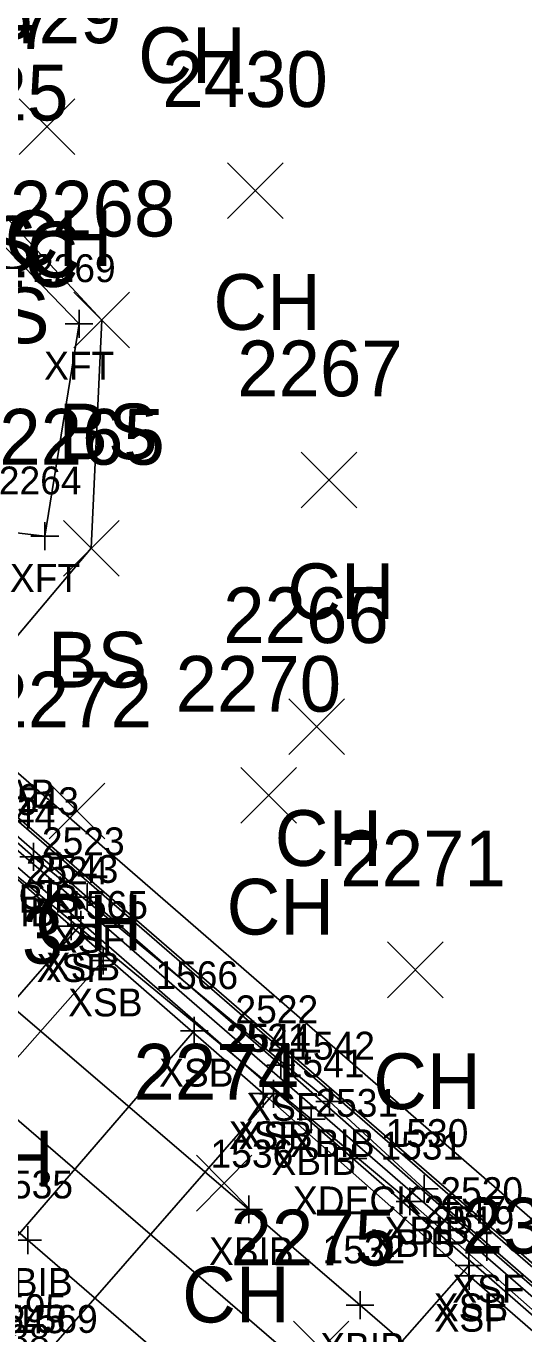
# Model space of a CAD drawing. Extents: x 1459992 to 1461532, y 647785 to 648535.
# Drawn here: x 1461313.18 to 1461331.07, y 648190.36 to 648237.31 of the extents above; entities that cross this region are included whole.
import ezdxf

# ---------------------------------------------------------------- set-up
doc = ezdxf.new("R2010")
doc.units = 0
for name, color, linetype in [('B_A', 7, 'Continuous'), ('B_C', 7, 'Continuous'), ('B_I', 7, 'Continuous'), ('B_TIC', 7, 'Continuous'), ('BB', 7, 'Continuous'), ('BDEFAULT', 7, 'Continuous'), ('BELB', 7, 'Continuous'), ('BFT', 7, 'Continuous'), ('L_A', 7, 'Continuous'), ('L_I', 7, 'Continuous'), ('L_TIC', 7, 'Continuous'), ('LELB', 7, 'Continuous')]:
    doc.layers.add(name, color=color, linetype=linetype)

msp = doc.modelspace()

# ---------------------------------------------------------------- linework, layer by layer
at = {"layer": 'B_TIC'}
for p, q in [((1461315.084, 648226.618), (1461315.16, 648226.618)), ((1461313.855, 648218.998), (1461313.931, 648218.998)), ((1461313.452, 648207.484), (1461313.528, 648207.484)), ((1461315.381, 648206.043), (1461315.456, 648206.043)), ((1461314.8, 648204.994), (1461314.876, 648204.994)), ((1461315.154, 648205.052), (1461315.229, 648205.052)), ((1461315.957, 648203.76), (1461316.032, 648203.76)), ((1461319.228, 648201.238), (1461319.303, 648201.238)), ((1461322.339, 648200.012), (1461322.414, 648200.012)), ((1461321.707, 648198.993), (1461321.782, 648198.993)), ((1461322.073, 648198.982), (1461322.148, 648198.982)), ((1461324.094, 648198.708), (1461324.169, 648198.708)), ((1461323.433, 648198.068), (1461323.508, 648198.068)), ((1461324.929, 648196.655), (1461325.004, 648196.655)), ((1461327.496, 648195.57), (1461327.572, 648195.57)), ((1461321.185, 648194.832), (1461321.261, 648194.832)), ((1461326.981, 648195.119), (1461327.057, 648195.119)), ((1461313.24, 648193.724), (1461313.315, 648193.724)), ((1461329.746, 648193.486), (1461329.822, 648193.486)), ((1461329.103, 648192.816), (1461329.178, 648192.816)), ((1461329.108, 648192.44), (1461329.184, 648192.44)), ((1461325.186, 648191.393), (1461325.262, 648191.393))]:
    msp.add_line(p, q, dxfattribs=at)
for points in [[(1461315.081, 648226.118), (1461315.081, 648227.118)], [(1461314.581, 648226.618), (1461315.581, 648226.618)], [(1461313.852, 648218.498), (1461313.852, 648219.498)], [(1461313.352, 648218.998), (1461314.352, 648218.998)], [(1461313.449, 648206.984), (1461313.449, 648207.984)], [(1461312.949, 648207.484), (1461313.949, 648207.484)], [(1461315.377, 648205.543), (1461315.377, 648206.543)], [(1461314.877, 648206.043), (1461315.877, 648206.043)], [(1461314.797, 648204.494), (1461314.797, 648205.494)], [(1461315.15, 648204.552), (1461315.15, 648205.552)], [(1461314.297, 648204.994), (1461315.297, 648204.994)], [(1461314.65, 648205.052), (1461315.65, 648205.052)], [(1461315.953, 648203.26), (1461315.953, 648204.26)], [(1461315.453, 648203.76), (1461316.453, 648203.76)], [(1461319.224, 648200.738), (1461319.224, 648201.738)], [(1461318.724, 648201.238), (1461319.724, 648201.238)], [(1461322.335, 648199.512), (1461322.335, 648200.512)], [(1461321.835, 648200.012), (1461322.835, 648200.012)], [(1461321.703, 648198.492), (1461321.703, 648199.493)], [(1461322.069, 648198.482), (1461322.069, 648199.482)], [(1461324.09, 648198.208), (1461324.09, 648199.208)], [(1461321.203, 648198.993), (1461322.203, 648198.993)], [(1461321.569, 648198.982), (1461322.569, 648198.982)], [(1461323.59, 648198.708), (1461324.59, 648198.708)], [(1461323.429, 648197.568), (1461323.429, 648198.568)], [(1461322.929, 648198.068), (1461323.929, 648198.068)], [(1461324.925, 648196.155), (1461324.925, 648197.155)], [(1461324.425, 648196.655), (1461325.425, 648196.655)], [(1461327.493, 648195.07), (1461327.493, 648196.07)], [(1461321.182, 648194.332), (1461321.182, 648195.332)], [(1461326.978, 648194.619), (1461326.978, 648195.619)], [(1461326.993, 648195.57), (1461327.993, 648195.57)], [(1461320.682, 648194.832), (1461321.682, 648194.832)], [(1461326.478, 648195.119), (1461327.478, 648195.119)], [(1461313.236, 648193.224), (1461313.236, 648194.224)], [(1461329.743, 648192.986), (1461329.743, 648193.986)], [(1461312.736, 648193.724), (1461313.736, 648193.724)], [(1461329.243, 648193.486), (1461330.243, 648193.486)], [(1461329.099, 648192.316), (1461329.099, 648193.316)], [(1461328.599, 648192.816), (1461329.599, 648192.816)], [(1461329.105, 648191.94), (1461329.105, 648192.94)], [(1461328.605, 648192.44), (1461329.605, 648192.44)], [(1461325.183, 648190.893), (1461325.183, 648191.893)], [(1461324.683, 648191.393), (1461325.683, 648191.393)]]:
    msp.add_lwpolyline(points, dxfattribs=at)
at = {"layer": 'BB'}
for points in [[(1461294.86, 648223.307), (1461364.242, 648163.24)], [(1461361.677, 648166.016), (1461348.554, 648177.299), (1461327.493, 648195.57), (1461324.09, 648198.708), (1461313.449, 648207.484), (1461303.185, 648216.496), (1461300.834, 648218.513)], [(1461361.208, 648165.406), (1461348.067, 648176.515), (1461326.978, 648195.119), (1461323.429, 648198.068), (1461312.601, 648206.996), (1461302.604, 648215.891), (1461300.353, 648217.975)], [(1461357.803, 648164.521), (1461346.033, 648173.409), (1461325.183, 648191.393), (1461321.182, 648194.832), (1461311.295, 648203.276), (1461301.649, 648211.621), (1461295.127, 648216.651)], [(1461353.847, 648159.998), (1461342.222, 648168.764), (1461326.194, 648182.545), (1461313.236, 648193.724), (1461305.462, 648200.447), (1461296.007, 648208.646)], [(1461306.331, 648194.965), (1461315.15, 648205.052)], [(1461315.953, 648203.76), (1461307.671, 648194.424)], [(1461319.224, 648201.238), (1461310.969, 648191.688)], [(1461322.069, 648198.982), (1461313.243, 648188.887)], [(1461320.229, 648182.764), (1461329.099, 648192.816)]]:
    msp.add_lwpolyline(points, dxfattribs=at)
at = {"layer": 'BDEFAULT'}
for points in [[(1461366.38, 648164.112), (1461295.255, 648225.766)], [(1461362.149, 648166.267), (1461362.72, 648165.994), (1461364.469, 648164.112), (1461295.876, 648223.48), (1461297.915, 648221.839), (1461297.913, 648221.848)], [(1461362.149, 648166.267), (1461297.913, 648221.848)], [(1461361.121, 648166.284), (1461352.416, 648173.806), (1461344.425, 648180.701), (1461343.816, 648181.296), (1461336.4, 648187.716), (1461329.743, 648193.486), (1461322.335, 648200.012), (1461315.377, 648206.043), (1461308.561, 648211.971), (1461301.731, 648217.881), (1461299.043, 648219.999)], [(1461360.363, 648157.144), (1461288.944, 648218.654)], [(1461360.571, 648165.346), (1461356.744, 648168.633), (1461349.668, 648174.685), (1461343.126, 648180.28), (1461343.115, 648180.272), (1461336.161, 648186.32), (1461329.105, 648192.44), (1461321.703, 648198.993), (1461314.797, 648204.994), (1461308.017, 648210.912), (1461301.203, 648216.737)]]:
    msp.add_lwpolyline(points, dxfattribs=at)
at = {"layer": 'BELB'}
msp.add_lwpolyline([(1461362.021, 648164.506), (1461356.918, 648168.766), (1461356.744, 648168.633), (1461346.243, 648178.153), (1461335.102, 648187.79), (1461324.925, 648196.655), (1461312.315, 648207.599), (1461296.583, 648221.232), (1461287.57, 648210.913), (1461301.391, 648198.959), (1461310.883, 648190.676), (1461320.988, 648181.882), (1461328.312, 648175.511), (1461338.631, 648166.593)], dxfattribs=at)
at = {"layer": 'BFT'}
msp.add_lwpolyline([(1461306.926, 648219.818), (1461313.852, 648218.998), (1461315.081, 648226.618), (1461311.483, 648230.338), (1461310.762, 648233.32)], dxfattribs=at)
at = {"layer": 'L_TIC'}
for points in [[(1461312.925, 648232.696), (1461314.925, 648234.696)], [(1461314.925, 648232.696), (1461312.925, 648234.696)], [(1461320.423, 648230.405), (1461322.423, 648232.405)], [(1461322.423, 648230.405), (1461320.423, 648232.405)], [(1461314.9, 648225.755), (1461316.9, 648227.755)], [(1461316.9, 648225.755), (1461314.9, 648227.755)], [(1461323.073, 648220.019), (1461325.073, 648222.019)], [(1461325.073, 648220.019), (1461323.073, 648222.019)], [(1461314.522, 648217.565), (1461316.522, 648219.565)], [(1461316.522, 648217.565), (1461314.522, 648219.565)], [(1461322.628, 648211.161), (1461324.628, 648213.161)], [(1461324.628, 648211.161), (1461322.628, 648213.161)], [(1461320.899, 648208.697), (1461322.899, 648210.697)], [(1461322.899, 648208.697), (1461320.899, 648210.697)], [(1461314.013, 648208.134), (1461316.013, 648210.134)], [(1461316.013, 648208.134), (1461314.013, 648210.134)], [(1461326.169, 648202.431), (1461328.169, 648204.431)], [(1461328.169, 648202.431), (1461326.169, 648204.431)], [(1461319.299, 648194.772), (1461321.299, 648196.772)], [(1461321.299, 648194.772), (1461319.299, 648196.772)], [(1461322.786, 648188.818), (1461324.786, 648190.818)], [(1461324.786, 648188.818), (1461322.786, 648190.818)]]:
    msp.add_lwpolyline(points, dxfattribs=at)
at = {"layer": 'LELB'}
msp.add_lwpolyline([(1461310.6, 648212.757), (1461315.522, 648218.565), (1461315.9, 648226.755), (1461312.011, 648230.923), (1461311.544, 648233.492), (1461310.733, 648233.836)], dxfattribs=at)

# ---------------------------------------------------------------- texts
at = {"layer": 'B_A'}
for s, p in [('XFT', (1461313.825, 648224.618)), ('XFT', (1461312.596, 648216.998)), ('XDECK', (1461310.158, 648205.599)), ('XBIB', (1461312.02, 648205.484)), ('XBIB', (1461311.172, 648204.996)), ('XSF', (1461314.137, 648204.043)), ('XSF', (1461313.557, 648202.994)), ('XSB', (1461313.886, 648203.052)), ('XSB', (1461314.69, 648201.76)), ('XSB', (1461317.96, 648199.238)), ('XSF', (1461321.095, 648198.012)), ('XSF', (1461320.463, 648196.993)), ('XSB', (1461320.805, 648196.982)), ('XBIB', (1461322.661, 648196.708)), ('XBIB', (1461322, 648196.068)), ('XDECK', (1461322.768, 648194.655)), ('XBIB', (1461326.064, 648193.57)), ('XBIB', (1461325.549, 648193.119)), ('XBIB', (1461319.753, 648192.832)), ('XBIB', (1461311.807, 648191.724)), ('XSF', (1461328.502, 648191.486)), ('XSB', (1461327.836, 648190.816)), ('XSF', (1461327.865, 648190.44)), ('XBIB', (1461323.754, 648189.393))]:
    msp.add_text(s, height=1, dxfattribs=at).set_placement(p)
at = {"layer": 'B_C'}
msp.add_text('CONC SLAB', height=1, dxfattribs=at).set_placement((1461306.502, 648209.257))
at = {"layer": 'B_I'}
for s, p in [('2269', (1461313.424, 648228.118)), ('2264', (1461312.198, 648220.498)), ('2532', (1461310.685, 648209.099)), ('1543', (1461312.102, 648208.984)), ('1544', (1461311.255, 648208.496)), ('2523', (1461313.747, 648207.543)), ('2524', (1461313.167, 648206.494)), ('2543', (1461313.52, 648206.552)), ('1565', (1461314.583, 648205.26)), ('1566', (1461317.826, 648202.738)), ('2522', (1461320.705, 648201.512)), ('2521', (1461320.357, 648200.493)), ('2544', (1461320.439, 648200.482)), ('1542', (1461322.744, 648200.208)), ('1541', (1461322.366, 648199.568)), ('2531', (1461323.579, 648198.155)), ('1530', (1461326.103, 648197.07)), ('1536', (1461319.808, 648196.332)), ('1531', (1461325.915, 648196.619)), ('1535', (1461311.89, 648195.224)), ('2520', (1461328.069, 648194.986)), ('2547', (1461327.469, 648194.316)), ('2519', (1461327.755, 648193.94)), ('1532', (1461323.836, 648192.893)), ('2595', (1461311.647, 648190.783)), ('2545', (1461311.613, 648190.387)), ('1569', (1461312.78, 648190.399)), ('2588', (1461311.054, 648189.703))]:
    msp.add_text(s, height=1, dxfattribs=at).set_placement(p)
at = {"layer": 'L_A'}
for s, p in [('CH', (1461317.207, 648235.265)), ('BS', (1461309.985, 648228.492)), ('CH', (1461312.414, 648228.696)), ('WALLC', (1461305.926, 648228.285)), ('WALLC', (1461305.839, 648227.944)), ('CH', (1461319.911, 648226.405)), ('BS', (1461310.452, 648225.923)), ('BS', (1461314.341, 648221.755)), ('CH', (1461322.561, 648216.019)), ('BS', (1461313.963, 648213.565)), ('CH', (1461322.116, 648207.161)), ('CH', (1461320.387, 648204.697)), ('CH', (1461313.501, 648204.134)), ('CH', (1461325.657, 648198.431)), ('CH', (1461310.313, 648195.652)), ('CH', (1461318.788, 648190.772))]:
    msp.add_text(s, height=2, dxfattribs=at).set_placement(p)
at = {"layer": 'L_I'}
for s, p in [('2428', (1461307.474, 648236.836)), ('2427', (1461308.284, 648236.492)), ('2429', (1461310.658, 648236.696)), ('2430', (1461318.076, 648234.405)), ('2425', (1461308.751, 648233.923)), ('2268', (1461312.593, 648229.755)), ('2267', (1461320.766, 648224.019)), ('2265', (1461312.215, 648221.565)), ('2266', (1461320.265, 648215.161)), ('2270', (1461318.553, 648212.697)), ('2272', (1461311.753, 648212.134)), ('2271', (1461324.476, 648206.431)), ('2273', (1461308.565, 648203.652)), ('2274', (1461317.04, 648198.772)), ('2275', (1461320.526, 648192.818)), ('2372', (1461328.837, 648193.245))]:
    msp.add_text(s, height=2, dxfattribs=at).set_placement(p)

doc.saveas('drawing.dxf')
